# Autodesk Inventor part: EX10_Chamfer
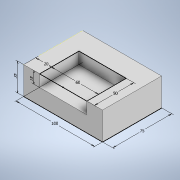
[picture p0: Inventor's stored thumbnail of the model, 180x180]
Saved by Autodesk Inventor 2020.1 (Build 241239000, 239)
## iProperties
Created: 2019-10
Part Number: EX10_Chamfer
Material: Generic
Document SubType Name: Modeling
Designer: Synergysoft Dell02
Density: 1 g/cm^3
Appearance: Default
Author: Synergysoft Dell02
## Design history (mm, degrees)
node "Annotations"
  node "Linear Dimension 1" dims "d4" = 100, "d5" = 75, "d13" = 15 (derived)
  node "Linear Dimension 2" dims "d4" = 100, "d5" = 75, "d16" = 35 (derived)
sketch "Sketch1"
  geometry: L1 (0, 0)-(-100, 0); L2 (-100, 0)-(-100, -75); L3 (-100, -75)-(0, -75); L4 (0, -75)-(0, 0)
  constraints: 8 end point, 2 parallel, 1 horizontal, 1 perpendicular
  dimensions: "d4" = 100 distance of L3.end L2.end; "d5" = 75 distance of L2.end L1.end
extrude "Extrusion1" new body sketch "Sketch1" distance "d2" = 35; taper "d3" = 0 deg
sketch "Sketch2"
  geometry: L1 (20, 0)-(80, 0); L2 (80, 0)-(80, 50); L3 (80, 50)-(20, 50); L4 (20, 50)-(20, 0); L5 (0, 75)-(0, 0) reference; 1 further point
  constraints: 8 end point, 2 parallel, 1 horizontal, 1 horizontal alignment, 1 midpoint, 1 perpendicular
  dimensions: "d6" = 60 distance of L3.end L2.end; "d7" = 20 distance between parallel lines of L4 L5; "d8" = 50 distance of L1.end L2.end
extrude "Extrusion2" cut sketch "Sketch2" distance "d9" = 15; taper "d10" = 0 deg
body "Solid1"
other parameters: "d11" = 0 (derived), "d14" = 0 (derived)
